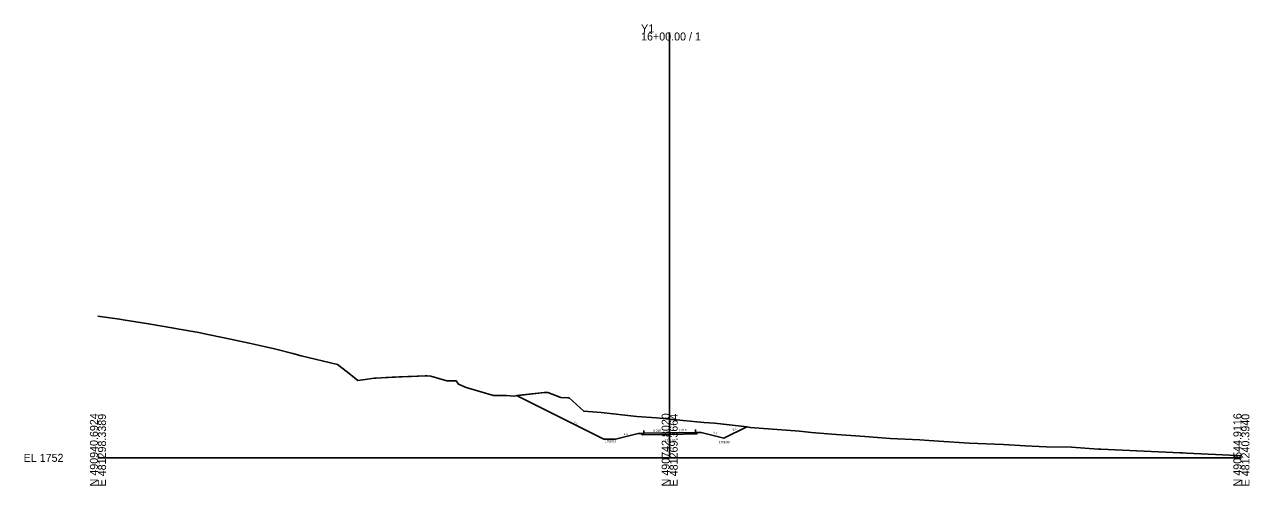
# Model space of a CAD drawing. Extents: x -26 to 403, y -10 to 6561.
# Drawn here: x -25.7 to 402.8, y 5990.3 to 6151.7 of the extents above; entities that cross this region are included whole.
import ezdxf

# ---------------------------------------------------------------- set-up
doc = ezdxf.new("R2010")
doc.units = 0
for name, color, linetype in [('Exist Cross Section Cell', 7, 'Continuous'), ('Exist XS Center Line Elevation Label', 7, 'Continuous'), ('Exist XS Ground Line', 7, 'Continuous'), ('Prop Road Sect_ Boring - Header (ID Tx)', 7, 'Continuous'), ('Prop Road Sect_ Material - Tx (Composite Desc)', 7, 'Continuous'), ('Prop XS Ditch Slope Text', 7, 'Continuous'), ('Prop XS Ditch Standard Text', 7, 'Continuous'), ('Prop XS EOT Tick Mark', 7, 'Continuous'), ('Prop XS Finish Grade', 7, 'Continuous'), ('Prop XS Finish Grade Earthwork', 7, 'Continuous'), ('Prop XS Finish Grade Pavement', 7, 'Continuous'), ('Prop XS Pvmt Edge Slope', 7, 'Continuous'), ('Prop XS SE Text', 7, 'Continuous'), ('Prop XS Side Slope Text', 7, 'Continuous'), ('Prop XS Subgrade Earthwork', 7, 'Continuous')]:
    doc.layers.add(name, color=color, linetype=linetype)

msp = doc.modelspace()

# ---------------------------------------------------------------- linework, layer by layer
at = {"layer": 'Exist Cross Section Cell'}
for p, q in [((200, 6000), (200, 6148.93)), ((0, 6000), (200, 6000)), ((200, 6000), (400, 6000))]:
    msp.add_line(p, q, dxfattribs=at)
at = {"layer": 'Exist XS Ground Line'}
msp.add_lwpolyline([(0, 6049.64), (7.55, 6048.56), (8.85, 6048.36), (17.71, 6046.94), (26.49, 6045.36), (27.77, 6045.14), (35.31, 6043.84), (37.88, 6043.29), (44.12, 6042.07), (47.99, 6041.23), (52.94, 6040.15), (58.1, 6039), (61.76, 6038.17), (68.21, 6036.5), (71.05, 6035.69), (83.84, 6032.68), (87.29, 6029.97), (90.96, 6027.05), (93.44, 6027.4), (96.67, 6027.9), (97.32, 6027.94), (99.09, 6028.02), (100.76, 6028.11), (101.62, 6028.15), (102.96, 6028.21), (104.14, 6028.25), (105.39, 6028.31), (106.41, 6028.38), (108.45, 6028.45), (109.17, 6028.48), (109.54, 6028.49), (111.69, 6028.58), (112.1, 6028.6), (114.5, 6028.69), (115.12, 6028.68), (116.43, 6028.55), (122.05, 6026.92), (125.36, 6026.91), (126.1, 6025.84), (128.8, 6024.64), (138.35, 6021.8), (142.94, 6021.79), (144.2, 6021.7), (145.2, 6021.64), (156.05, 6022.91), (157.38, 6022.84), (161.92, 6021.18), (164.32, 6021.03), (164.87, 6020.98), (169.97, 6016.33), (175.99, 6015.87), (188.48, 6014.48), (195.37, 6013.95), (200, 6013.53), (212, 6012.43), (215.63, 6012.14), (227.14, 6010.8), (227.62, 6010.75), (228.11, 6010.67), (245.46, 6009.33), (249.66, 6008.85), (256.72, 6008.3), (268.25, 6007.47), (277.16, 6006.81), (287.51, 6006.25), (290.71, 6006.07), (294.2, 6005.8), (304.76, 6005.18), (316.73, 6004.66), (324.37, 6004.26), (331.66, 6003.88), (340.6, 6003.72), (349.95, 6003), (350.29, 6003), (350.79, 6002.98), (378.55, 6001.75), (379.42, 6001.72), (380.9, 6001.6), (398.45, 6000.8), (400, 6000.73)], dxfattribs=at)
at = {"layer": 'Prop Road Sect_ Boring - Header (ID Tx)'}
for points in [[(191, 6008.59), (190.45, 6008.04), (189.94, 6008.55)], [(209, 6008.91), (209.93, 6008.87), (209.53, 6008.38)]]:
    msp.add_lwpolyline(points, close=True, dxfattribs=at)
at = {"layer": 'Prop Road Sect_ Material - Tx (Composite Desc)'}
msp.add_lwpolyline([(177, 6006.51), (146.45, 6021.78), (156.05, 6022.91), (157.38, 6022.84), (161.92, 6021.18), (164.32, 6021.03), (164.87, 6020.98), (169.97, 6016.33), (175.99, 6015.87), (188.48, 6014.48), (195.37, 6013.95), (200, 6013.53), (212, 6012.43), (215.63, 6012.14), (226.98, 6010.82), (219, 6006.83), (211, 6008.83), (209.93, 6008.87), (209.53, 6008.38), (200.01, 6008.21), (190.45, 6008.04), (189.94, 6008.55), (189, 6008.51), (181, 6006.51)], close=True, dxfattribs=at)
at = {"layer": 'Prop XS EOT Tick Mark'}
for p, q in [((191, 6008.59), (191, 6009.59)), ((209, 6008.91), (209, 6009.91))]:
    msp.add_line(p, q, dxfattribs=at)
at = {"layer": 'Prop XS Finish Grade'}
for p, q in [((191, 6008.59), (189.94, 6008.55)), ((209, 6008.91), (209.93, 6008.87))]:
    msp.add_line(p, q, dxfattribs=at)
at = {"layer": 'Prop XS Finish Grade Earthwork'}
for p, q in [((177, 6006.51), (146.45, 6021.78)), ((189, 6008.51), (181, 6006.51)), ((189, 6008.51), (189.94, 6008.55)), ((211, 6008.83), (209.93, 6008.87)), ((211, 6008.83), (219, 6006.83)), ((219, 6006.83), (226.98, 6010.82)), ((181, 6006.51), (177, 6006.51))]:
    msp.add_line(p, q, dxfattribs=at)
at = {"layer": 'Prop XS Finish Grade Pavement'}
for p, q in [((191, 6008.59), (200, 6008.75)), ((200, 6008.75), (209, 6008.91))]:
    msp.add_line(p, q, dxfattribs=at)
at = {"layer": 'Prop XS Pvmt Edge Slope'}
for p, q in [((191, 6008.59), (190.45, 6008.04)), ((209, 6008.91), (209.53, 6008.38))]:
    msp.add_line(p, q, dxfattribs=at)
at = {"layer": 'Prop XS Subgrade Earthwork'}
for p, q in [((189.94, 6008.55), (190.45, 6008.04)), ((190.45, 6008.04), (200.01, 6008.21)), ((200.01, 6008.21), (209.53, 6008.38)), ((209.93, 6008.87), (209.53, 6008.38))]:
    msp.add_line(p, q, dxfattribs=at)

# ---------------------------------------------------------------- texts
at = {"layer": 'Exist Cross Section Cell'}
for s, p in [('Y1', (190, 6148.93)), ('16+00.00 / 1', (190, 6146.13)), ('EL 1752', (-26, 5998.6))]:
    msp.add_text(s, height=2.8, dxfattribs=at).set_placement(p)
for s, p in [('N 490940.6924', (0, 5990)), ('E 481298.3389', (2.8, 5990)), ('N 490742.8020', (200, 5990)), ('E 481269.3664', (202.8, 5990)), ('N 490544.9116', (400, 5990)), ('E 481240.3940', (402.8, 5990))]:
    msp.add_text(s, height=2.8, rotation=90, dxfattribs=at).set_placement(p)
at = {"layer": 'Exist XS Center Line Elevation Label'}
msp.add_text('1765.53', height=0.75, dxfattribs=at).set_placement((198.28, 6005.72))
at = {"layer": 'Prop XS Ditch Slope Text'}
for rotation, p in [(14.0362, (184.04, 6007.81)), (345.9638, (215.28, 6008.57))]:
    msp.add_text('4:1', height=0.75, rotation=rotation, dxfattribs=at).set_placement(p)
at = {"layer": 'Prop XS Ditch Standard Text'}
for s, p in [('1758.51', (177.42, 6005.46)), ('1758.83', (217.2, 6005.13))]:
    msp.add_text(s, height=0.75, dxfattribs=at).set_placement(p)
at = {"layer": 'Prop XS SE Text'}
for p in [(194.26, 6009.15), (203.26, 6009.31)]:
    msp.add_text('0.018', height=0.75, rotation=1.0312, dxfattribs=at).set_placement(p)
at = {"layer": 'Prop XS Side Slope Text'}
for rotation, p in [(333.4349, (166.31, 6012.11)), (26.5651, (222.18, 6009.36))]:
    msp.add_text('2:1', height=0.75, rotation=rotation, dxfattribs=at).set_placement(p)

doc.saveas('drawing.dxf')
